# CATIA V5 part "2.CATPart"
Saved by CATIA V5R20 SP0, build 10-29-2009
Part number: 2
Material "Steel": density 7860 kg/m3, Young's modulus 2e+11 Pa, Poisson ratio 0.266, thermal expansion 1.17e-05 1/K
Bounding box of the stored display mesh (mm): x 0 to 650, y -1 to 240, z -115 to 22
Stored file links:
  E:\Ehsan\Amoozesh\CATIA\CATIA Course\Advanced\Videos\Session-13\2.CATPart
  D:\CATIA V5R20\B20\intel_a\startup\materials\Catalog.CATMaterial
  D:\CATIA V5R20\B20\intel_a\resources\graphic\figures\CATIA_EnvironmentMap_Potsdamer_512x512.jpg
  D:\CATIA V5R20\B20\intel_a\resources\graphic\figures\CATIA_EnvironmentMap_Garden_512x512.jpg
  D:\CATIA V5R20\B20\intel_a\resources\graphic\figures\CATIA_EnvironmentMap_Road_512x512.jpg
  D:\CATIA V5R20\B20\intel_a\resources\graphic\figures\CATIA_EnvironmentMap_Field_512x512.jpg
  D:\CATIA V5R20\B20\intel_a\resources\graphic\figures\CATIA_EnvironmentMap_Street_512x512.jpg
  D:\CATIA V5R20\B20\intel_a\resources\graphic\figures\CATIA_EnvironmentMap_Hall_512x512.jpg
  D:\CATIA V5R20\B20\intel_a\resources\graphic\figures\CATIA_EnvironmentMap_Satin_512x512.jpg
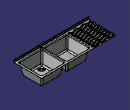
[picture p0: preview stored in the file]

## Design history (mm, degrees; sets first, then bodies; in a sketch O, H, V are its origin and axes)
SheetMetalParameters1: Thickness 1, BendRadius 2, KFactor 0.400515 {= log(min(100,max(20*SheetMetalParameters1.BendRadius,SheetMetalParameters1.Thickness)/SheetMetalParameters1.Thickness))/log(100)/2}, ReliefRadialLength 1, ReliefAxialLength 2, MinimumBendRadius 0
Body1 (main body), material "Steel"
  Sketch1 on xy-plane, origin (0, 0, 0), H (1, 0, 0), V (0, 1, 0)
    line L1 (0, 0) -> (650, 0)
    line L2 (650, 0) -> (650, 240)
    line L3 (650, 240) -> (0, 240)
    line L4 (0, 240) -> (0, 0)
    distance L1 L3 = 240
    distance L2 L4 = 650
    horizontal: L1 H, L3 H
    vertical: L2 V, L4 V
  Wall1: Thickness 1, Profile Sketch1
  d_NewWallOnEdge1: NewWallOnEdge_Length 20, NewWallOnEdge_HeightLimitOffset 0, NewWallOnEdge_WidthOffset1 0, NewWallOnEdge_WidthOffset2 0, NewWallOnEdge_Angle 90, NewWallOnEdge_BendRadiusValue 2 {= SheetMetalParameters1.BendRadius}, NewWallOnEdge_BendTable SheetMetalParameters1, NewWallOnEdge_Edge edge [face of Wall1 | face of Wall1], NewWallOnEdge_GapValue 0, KFacteur 0.400515 {= log(min(100,max(20*d_NewWallOnEdge1.Radius,SheetMetalParameters1.Thickness)/SheetMetalParameters1.Thickness))/log(100)/2}
  Flange1: Angle 22.6199 {= 2*atan(Flange1.Radius/Flange1.Length)}, KFacteur 0.325257 {= log(min(100,max(20*Flange1.Radius,SheetMetalParameters1.Thickness)/SheetMetalParameters1.Thickness))/log(100)/2}, Length 5, Radius 1, Guide edge [face of d_NewWallOnEdge1 | face of d_NewWallOnEdge1]
  d_Stamp1: NewRoot_AttribNormalisation "No Standard", Stamp_FilletRadius 5, Stamp_IntersectFilletRadius 2
  d_Stamp2: NewRoot_AttribNormalisation "No Standard", Stamp_FilletRadius 5, Stamp_IntersectFilletRadius 2
  d_Stamp3: NewRoot_AttribNormalisation "No Standard", Stamp_FilletRadius 5, Stamp_IntersectFilletRadius 2
  CutOut1: Direction Sketch3, EndLimit through (limit type 2), Orientation true, Profile Sketch3, StartLimit through (limit type 2)
  CutOut2: Direction Sketch2, EndLimit through (limit type 2), Orientation true, Profile Sketch2, StartLimit through (limit type 2)
  Sketch2 on face of Wall1, origin (0, 0, 0), H (1, 0, 0), V (0, -1, 0)
    circle A1 centre (420, -12.9654) radius 8
    point P1 (420, -12.9654)
    reference projected line E1 (440.7223, -14.9654) -> (619.2777, -14.9654) from edge [face of d_Stamp1 | face of Wall1]
    radius A1 = 8
    distance P1 E1 = 2
  Sketch3 on face of d_Stamp3, origin (0, 0, -114), H (1, 0, 0), V (0, 1, 0)
    point P1 (480, 70)
    circle A1 centre (470, 70) radius 2
    circle A2 centre (476.9098, 60.4894) radius 2
    circle A3 centre (488.0902, 64.1221) radius 2
    circle A4 centre (488.0902, 75.8779) radius 2
    circle A5 centre (476.9098, 79.5106) radius 2
    point P7 (360, 70)
    circle A6 centre (350, 70) radius 2
    circle A7 centre (356.9098, 60.4894) radius 2
    circle A8 centre (368.0902, 64.1221) radius 2
    circle A9 centre (368.0902, 75.8779) radius 2
    circle A10 centre (356.9098, 79.5106) radius 2
    radius A1 = 2
    radius A6 = 2
  Sketch4 on face of d_Stamp1, origin (0, 0, -99), H (1, 0, 0), V (0, 1, 0)
    circle A1 centre (360, 70) radius 20
    circle A2 centre (480, 70) radius 20
  Sketch5 on face of Wall1, origin (0, 0, 1), H (1, 0, 0), V (0, 1, 0)
    spline S1 through (10, 20) (40, 30) (70, 20) (100, 30) (130, 20) (160, 30) (190, 20)
    spline S2 through (10, 45) (40, 55) (70, 45) (100, 55) (130, 45) (160, 55) (190, 45)
    spline S3 through (10, 70) (40, 80) (70, 70) (100, 80) (130, 70) (160, 80) (190, 70)
    spline S4 through (10, 95) (40, 105) (70, 95) (100, 105) (130, 95) (160, 105) (190, 95)
    spline S5 through (10, 120) (40, 130) (70, 120) (100, 130) (130, 120) (160, 130) (190, 120)
    spline S6 through (10, 145) (40, 155) (70, 145) (100, 155) (130, 145) (160, 155) (190, 145)
    spline S7 through (10, 170) (40, 180) (70, 170) (100, 180) (130, 170) (160, 180) (190, 170)
    spline S8 through (10, 195) (40, 205) (70, 195) (100, 205) (130, 195) (160, 205) (190, 195)
    spline S9 through (10, 220) (40, 230) (70, 220) (100, 230) (130, 220) (160, 230) (190, 220)
  Sketch6 on face of Wall1, origin (0, 0, 1), H (1, 0, 0), V (0, 1, 0)
    line L1 (630, 220) -> (430, 220)
    line L2 (430, 220) -> (430, 20)
    line L3 (430, 20) -> (630, 20)
    line L4 (630, 20) -> (630, 220)
    reference projected line E1 (650, 0) -> (650, 240) from edge [face of Wall1 | face of Wall1]
    reference projected line E2 (600, 240) -> (0, 240) from edge [face of Wall1 | face of Wall1]
    line L5 (410, 20) -> (410, 220)
    line L6 (210, 20) -> (410, 20)
    line L7 (210, 220) -> (210, 20)
    line L8 (410, 220) -> (210, 220)
    distance L4 E1 = 20
    distance L1 E2 = 20
    length L1 = 200
    length L4 = 200
    distance L5 L2 = 20
    distance L8 L6 = 200
    distance L7 L5 = 200
    horizontal: L1 H, L3 H, L6 H, L8 H
    vertical: L2 V, L4 V, L5 V, L7 V
    perpendicularity: L7 L8
    coincidence: L6 L3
